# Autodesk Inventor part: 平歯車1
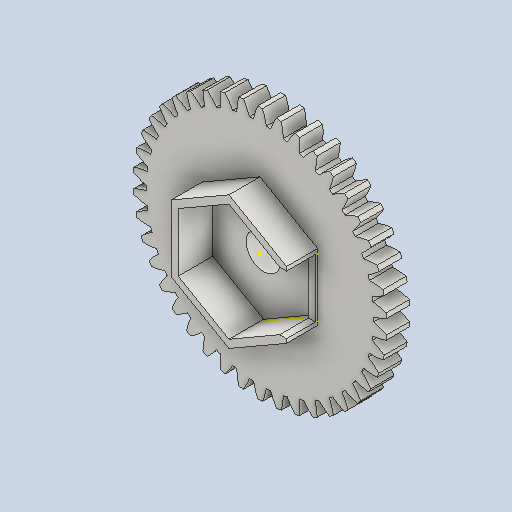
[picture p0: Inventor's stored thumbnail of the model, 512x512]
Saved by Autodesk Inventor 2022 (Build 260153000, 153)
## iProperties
CustomPartVersion: 1
Created: 2024-11
Part Number: 平歯車1
Material: Steel
Document SubType Name: Modeling
Designer: neo09
Categories: <?xml version="1.0" encoding="UTF-16"?> <MemberInstance><Categories><FamilyTemplate><FamilyTemplateParameter ValueType="xs:double" Id="1" ObjectReferenceKey="da
Density: 1 g/cm^3
Appearance: Steel
Author: neo09
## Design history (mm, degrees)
sketch "Sketch1"
  geometry: C1 r 11 at (0, 0)
  constraints: 1 centre point
  dimensions: "d0" = 22 diameter of C1 (= da_da)
extrude "Extrusion1" new body sketch "Sketch1" distance "d1" = 2 (= da_b); taper "d2" = 0 deg
workplane "Work Plane2"
sketch "Sketch2"
  geometry: C1 r 11 at (0, 0) reference; C2 r 10.5 at (0, 0)
  constraints: 1 centre point, 1 coincident
  dimensions: "d3" = 21 diameter of C2 (= da_d)
feature "ピッチ円直径" sketch "Sketch2" dims "d4" = 10, "d5" = 0
workplane "Work Plane8"
workplane "Work Plane9"
feature "平歯車" dims "da_b" = 2, "da_d" = 21, "da_aw" = 24.75, "da_da" = 22, "da_df" = 19.75, "da_dw" = 21, angle "da_beta" = 0 deg, "da_lefttooth" = 0, "da_righttooth" = 0
sketch "スケッチ3"
  geometry: L1 (0, 5.774)-(5, 2.887); L2 (5, -2.887)-(0, -5.774); L3 (0, -5.774)-(-5, -2.887); L4 (-5, -2.887)-(-5, 2.887); L5 (-5, 2.887)-(0, 5.774); L6 (0, 5.081)-(4.4, 2.54); L7 (4.4, -2.54)-(0, -5.081); L8 (0, -5.081)-(-4.4, -2.54); L9 (-4.4, -2.54)-(-4.4, 2.54); L10 (-4.4, 2.54)-(0, 5.081); L11 (4.4, 2.54)-(5, 2.54); L12 (4.4, -2.54)-(5, -2.54); L13 (5, 2.887)-(5, 2.54); L14 (5, -2.54)-(5, -2.887); 4 further points
  constraints: 28 end point, 2 coincident, 2 perpendicular, 1 horizontal, 22 other
  dimensions: "d49" = 10 distance between parallel lines of L3 L1; "d50" = 8.8 distance between parallel lines of L7 L10
extrude "押し出し2" join sketch "スケッチ3" distance "d51" = 2.7; taper "d52" = 0 deg
sketch "スケッチ4"
  geometry: L1 (0, 5.081)-(-4.4, 2.54) reference; L2 (0, 5.081)-(4.4, 2.54); L3 (4.4, 2.54)-(4.4, -2.54); L4 (4.4, -2.54)-(0, -5.081); L5 (0, -5.081)-(-4.4, -2.54); L6 (-4.4, -2.54)-(-4.4, 2.54); L7 (-4.4, 2.54)-(0, 5.081); 3 further points
  constraints: 12 end point, 1 coincident, 13 other
extrude "押し出し3" cut sketch "スケッチ4" distance "d53" = 0.3; taper "d54" = 0 deg
sketch "スケッチ8"
  geometry: L1 (4.4, 2.54)-(4.4, -2.54) reference; L2 (4.4, 2.54)-(5, 2.54) reference; L3 (4.4, 2.54)-(5, 2.54); L4 (5, -2.54)-(4.4, -2.54) reference; L5 (5, 2.54)-(5, -2.54); L6 (5, -2.54)-(4.4, -2.54); L7 (0, 5.081)-(4.4, 2.54) reference; L8 (4.4, -2.54)-(4.4, 2.54); 1 further point
  constraints: 8 end point, 3 perpendicular, 1 collinear
extrude "押し出し4" join sketch "スケッチ8" distance "d55" = 0.2; taper "d56" = 0 deg
sketch "スケッチ9"
  geometry: C1 r 1.5 at (0, 0); 1 further point
  constraints: 1 centre point, 1 coincident
  dimensions: "d57" = 3 diameter of C1
extrude "押し出し5" cut sketch "スケッチ9" distance "d58" = 3; taper "d59" = 0 deg
body "Solid1"
sketch "スケッチ5"
  geometry: L1 (4.4, 2.54)-(5, 2.54) reference; L2 (5, -2.54)-(4.4, -2.54) reference; 1 further point
sketch "スケッチ6"
  geometry: L1 (4.4, 2.54)-(4.4, -2.54) reference; L2 (0, 5.081)-(4.4, 2.54) reference; L3 (4.4, 2.54)-(5, 2.54) reference; L4 (5, -2.54)-(4.4, -2.54) reference; L5 (4.4, -2.54)-(0, -5.081) reference; 1 further point
sketch "スケッチ7"
  geometry: 1 further point
body "Srf1"
other parameters: "d16" = 24.75 (= da_aw), "d17" = 0, "d34" = 0.748 (computed from da_z), "d39" = 0, "d41" = 0, "d43" = 24.75 (= da_aw), "d46" = 24.75 (= da_aw), "d47" = 0, "d48" = 0
